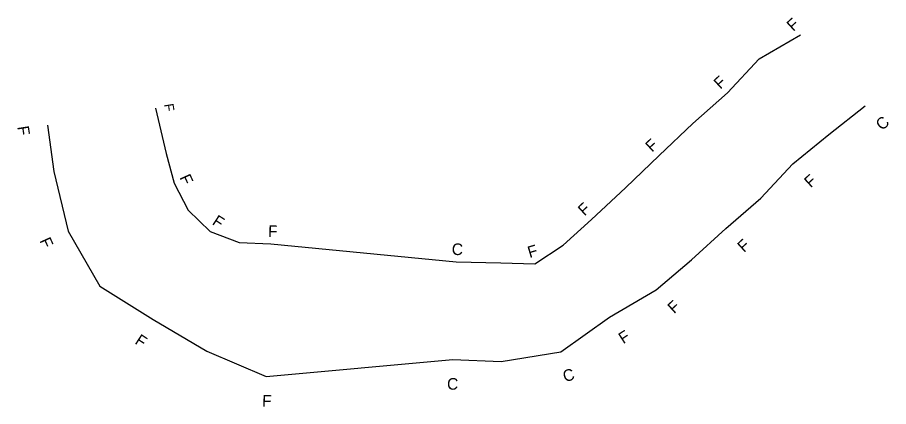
# Model space of a CAD drawing. Extents: x 1191394 to 1191753, y 892994 to 893350.
# Drawn here: x 1191394 to 1191581.6, y 892993.6 to 893077.4 of the extents above; entities that cross this region are included whole.
import ezdxf

# ---------------------------------------------------------------- set-up
doc = ezdxf.new("R2010")
doc.units = 0
for name, color, linetype in [('Prop DSN Text', 7, 'Continuous'), ('Prop SS Cut Line', 7, 'Continuous'), ('Prop SS Fill Line', 7, 'Continuous'), ('Prop SS Transition Line', 7, 'Continuous')]:
    doc.layers.add(name, color=color, linetype=linetype)

msp = doc.modelspace()

# ---------------------------------------------------------------- linework, layer by layer
at = {"layer": 'Prop SS Cut Line'}
for p, q in [((1191568.74, 893052.13), (1191576.6, 893058.35)), ((1191488.48, 893024.71), (1191498.09, 893024.49)), ((1191498.15, 893003.3), (1191511.03, 893005.33)), ((1191487.74, 893003.71), (1191498.15, 893003.3))]:
    msp.add_line(p, q, dxfattribs=at)
at = {"layer": 'Prop SS Fill Line'}
for p, q in [((1191553.76, 893068.45), (1191562.62, 893073.59)), ((1191546.89, 893061.15), (1191553.76, 893068.45)), ((1191539.43, 893054.49), (1191546.89, 893061.15)), ((1191423.71, 893057.8), (1191426.01, 893048.04)), ((1191400.48, 893054.13), (1191401.85, 893044.22)), ((1191532.18, 893047.6), (1191539.43, 893054.49)), ((1191426.01, 893048.04), (1191427.77, 893041.64)), ((1191524.97, 893040.67), (1191532.18, 893047.6)), ((1191554.12, 893038.48), (1191560.96, 893045.82)), ((1191401.85, 893044.22), (1191404.93, 893031.33)), ((1191427.77, 893041.64), (1191430.79, 893035.88)), ((1191517.64, 893033.86), (1191524.97, 893040.67)), ((1191546.58, 893031.91), (1191554.12, 893038.48)), ((1191430.79, 893035.88), (1191435.53, 893031.25)), ((1191511.52, 893028.3), (1191517.64, 893033.86)), ((1191404.93, 893031.33), (1191411.72, 893019.49)), ((1191435.53, 893031.25), (1191441.73, 893028.92)), ((1191539.17, 893025.19), (1191546.58, 893031.91)), ((1191441.73, 893028.92), (1191448.59, 893028.6)), ((1191505.4, 893024.29), (1191511.52, 893028.3)), ((1191531.55, 893018.71), (1191539.17, 893025.19)), ((1191411.72, 893019.49), (1191423.24, 893012.29)), ((1191521.54, 893012.81), (1191531.55, 893018.71)), ((1191423.24, 893012.29), (1191434.77, 893005.54)), ((1191434.77, 893005.54), (1191447.59, 893000.07))]:
    msp.add_line(p, q, dxfattribs=at)
at = {"layer": 'Prop SS Transition Line'}
for p, q in [((1191560.96, 893045.82), (1191568.74, 893052.13)), ((1191448.59, 893028.6), (1191488.48, 893024.71)), ((1191498.09, 893024.49), (1191505.4, 893024.29)), ((1191511.03, 893005.33), (1191521.54, 893012.81)), ((1191447.59, 893000.07), (1191487.74, 893003.71))]:
    msp.add_line(p, q, dxfattribs=at)

# ---------------------------------------------------------------- texts
at = {"layer": 'Prop DSN Text'}
for s, height, rotation, p in [('F', 2.5, 42.5411, (1191561.08, 893074.22)), ('F', 2.5, 42.5411, (1191545.36, 893061.78)), ('F', 2.05, 278.9764, (1191425.55, 893058.64)), ('C', 2.5, 42.5411, (1191580.24, 893052.87)), ('F', 2.5, 278.9764, (1191393.95, 893053.81)), ('F', 2.5, 42.5411, (1191530.65, 893048.22)), ('F', 2.5, 294.3006, (1191428.84, 893042.91)), ('F', 2.5, 42.5411, (1191564.84, 893040.55)), ('F', 2.5, 42.5411, (1191516.11, 893034.49)), ('F', 2.5, 327.0412, (1191435.76, 893032.89)), ('F', 2.5, 357.9944, (1191447.94, 893030.12)), ('F', 2.5, 294.3006, (1191398.71, 893029.3)), ('F', 2.5, 42.5411, (1191550.46, 893026.64)), ('C', 2.5, 357.9944, (1191487.5, 893026.24)), ('F', 2.5, 16.5395, (1191504.3, 893025.53)), ('F', 2.5, 42.5411, (1191535.42, 893013.44)), ('F', 2.5, 327.0412, (1191419.11, 893007.23)), ('F', 2.5, 32.9097, (1191524.48, 893006.97)), ('C', 2.5, 16.5395, (1191511.89, 892998.81)), ('C', 2.5, 357.9944, (1191486.48, 892997.26)), ('F', 2.5, 357.9944, (1191446.66, 892993.6))]:
    msp.add_text(s, height=height, rotation=rotation, dxfattribs=at).set_placement(p)

doc.saveas('drawing.dxf')
